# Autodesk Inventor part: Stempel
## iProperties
Created: 2006-03
Part Number: Stempel
Document SubType Name: Modeling
Designer: Henseler
Author: Henseler
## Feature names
1. Extrusion1
2. Extrusion2
3. Drehung1 [Revolution]
4. Fase1 [Chamfer]
